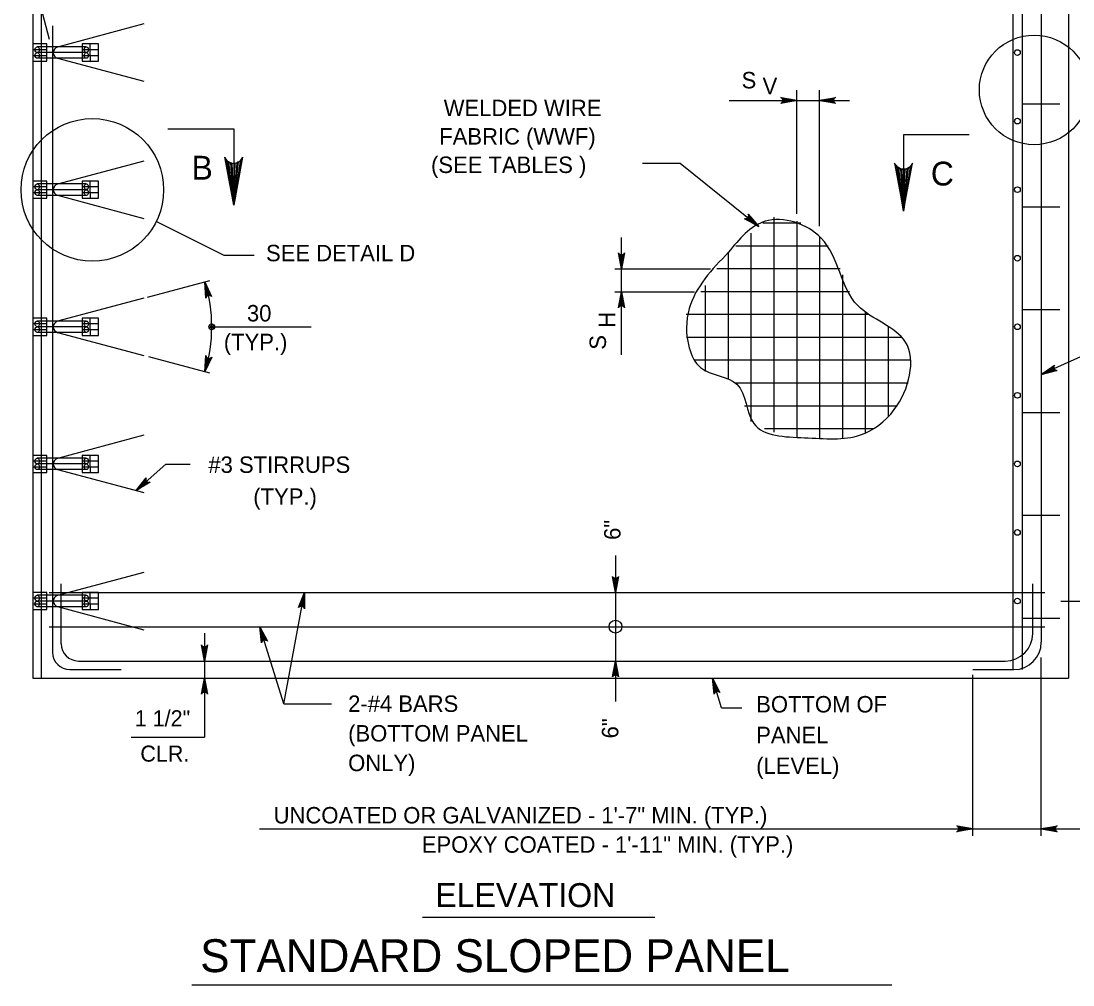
# Model space of a CAD drawing. Extents: x 3385 to 6532, y -616 to 1166.
# Drawn here: x 5133.3 to 5329.7, y 272.4 to 452.4 of the extents above; entities that cross this region are included whole.
import ezdxf

# ---------------------------------------------------------------- set-up
doc = ezdxf.new("R2010")
doc.units = 0
doc.layers.add('1', color=7, linetype='Continuous')

msp = doc.modelspace()

# ---------------------------------------------------------------- linework, layer by layer
at = {"layer": '1'}
for p, q in [((5135.5, 484.9), (5135.5, 329.7)), ((5137.06, 484.9), (5137.06, 329.7)), ((5318.4, 472.1), (5318.4, 331.3)), ((5320.15, 472.1), (5320.15, 331.3)), ((5328.8, 472.1), (5328.8, 329.7)), ((5323.74, 465.38), (5323.74, 336.42)), ((5138.61, 448.92), (5137.35, 453.64)), ((5156.21, 451.84), (5140.09, 447.52)), ((5139.2, 451.51), (5139.2, 334.5)), ((5146.23, 445.97), (5146.23, 448.1)), ((5145.48, 447.57), (5136.32, 447.57)), ((5145.48, 446.5), (5136.32, 446.5)), ((5146.23, 445.97), (5146.23, 444.9)), ((5145.48, 445.44), (5136.32, 445.44)), ((5140.09, 445.46), (5156.21, 441.14)), ((5278.08, 416.38), (5278.08, 439.45)), ((5282.35, 414.07), (5282.35, 439.45)), ((5265.47, 437.57), (5287.91, 437.57)), ((5320.29, 436.9), (5327.2, 436.9)), ((5160.72, 432.26), (5172.99, 432.26)), ((5172.99, 432.26), (5172.99, 417.99)), ((5310.3, 431.16), (5298.04, 431.16)), ((5298.04, 431.16), (5298.04, 416.9)), ((5156.21, 426.24), (5140.09, 421.92)), ((5249.28, 425.88), (5256.32, 425.88)), ((5256.32, 425.88), (5271.01, 414.01)), ((5146.23, 420.37), (5146.23, 422.5)), ((5145.48, 421.97), (5136.32, 421.97)), ((5145.48, 420.9), (5136.32, 420.9)), ((5146.23, 420.37), (5146.23, 419.3)), ((5145.48, 419.84), (5136.32, 419.84)), ((5140.09, 419.86), (5156.21, 415.54)), ((5320.29, 417.7), (5327.2, 417.7)), ((5171.24, 408.59), (5158.53, 414.93)), ((5278.87, 414.65), (5271.76, 414.65)), ((5273.82, 415.79), (5273.82, 375.64)), ((5278.08, 415.04), (5278.08, 374.75)), ((5269.55, 412.77), (5269.55, 377.6)), ((5245.37, 390.05), (5245.37, 411.96)), ((5283.94, 410.38), (5266.72, 410.38)), ((5282.35, 412.14), (5282.35, 374.37)), ((5176.84, 408.59), (5171.24, 408.59)), ((5265.28, 409.12), (5265.28, 385.48)), ((5244.14, 406.11), (5262.01, 406.11)), ((5286.17, 406.11), (5263.18, 406.11)), ((5286.62, 404.98), (5286.62, 374.45)), ((5156.91, 400.83), (5168.52, 403.94)), ((5261.02, 403.02), (5261.02, 386.97)), ((5156.21, 400.64), (5140.09, 396.32)), ((5244.14, 401.85), (5259.02, 401.85)), ((5287.91, 401.85), (5260.2, 401.85)), ((5146.23, 394.77), (5146.23, 396.9)), ((5291.37, 397.58), (5257.46, 397.58)), ((5290.88, 397.94), (5290.88, 375.43)), ((5320.29, 398.5), (5327.2, 398.5)), ((5145.48, 396.37), (5136.32, 396.37)), ((5145.48, 395.3), (5136.32, 395.3)), ((5146.23, 394.77), (5146.23, 393.7)), ((5168.9, 395.29), (5187.48, 395.29)), ((5295.15, 395.28), (5295.15, 378.54)), ((5145.48, 394.24), (5136.32, 394.24)), ((5140.09, 394.26), (5156.21, 389.94)), ((5297.71, 393.31), (5257.51, 393.31)), ((5335.79, 391.81), (5323.74, 386.42)), ((5168.52, 386.64), (5157.13, 389.7)), ((5299.38, 389.05), (5259.09, 389.05)), ((5298.86, 384.78), (5266.66, 384.78)), ((5296.82, 380.51), (5268.32, 380.51)), ((5320.29, 379.3), (5327.2, 379.3)), ((5156.21, 375.04), (5140.09, 370.72)), ((5292.45, 376.25), (5272.09, 376.25)), ((5146.23, 369.17), (5146.23, 371.3)), ((5145.48, 370.77), (5136.32, 370.77)), ((5145.48, 369.7), (5136.32, 369.7)), ((5146.23, 369.17), (5146.23, 368.1)), ((5160.32, 369.64), (5154.78, 364.73)), ((5160.32, 369.64), (5164.86, 369.64)), ((5145.48, 368.64), (5136.32, 368.64)), ((5140.09, 368.66), (5156.21, 364.34)), ((5320.29, 360.1), (5327.2, 360.1)), ((5244.27, 352.58), (5244.27, 325.36)), ((5156.21, 349.44), (5140.09, 345.12)), ((5138.56, 345.7), (5324.39, 345.7)), ((5140.8, 336.1), (5140.8, 347.3)), ((5146.23, 343.57), (5146.23, 345.7)), ((5182.33, 324.9), (5186.19, 345.7)), ((5322.14, 338.02), (5322.14, 347.3)), ((5145.48, 345.17), (5136.32, 345.17)), ((5145.48, 344.1), (5136.32, 344.1)), ((5327.41, 344.1), (5385.83, 344.1)), ((5145.48, 343.04), (5136.32, 343.04)), ((5140.09, 343.06), (5156.21, 338.75)), ((5146.23, 343.57), (5146.23, 342.5)), ((5320.29, 340.9), (5327.2, 340.9)), ((5138.56, 339.3), (5324.39, 339.3)), ((5167.54, 338.1), (5167.54, 318.71)), ((5182.33, 324.9), (5177.86, 339.3)), ((5144, 332.9), (5317.02, 332.9)), ((5323.74, 300.25), (5323.74, 333.55)), ((5142.4, 331.3), (5152, 331.3)), ((5310.94, 331.3), (5318.62, 331.3)), ((5310.94, 300.25), (5310.94, 330.3)), ((5135.5, 329.7), (5328.8, 329.7)), ((5264.06, 324.18), (5262.34, 329.7)), ((5182.33, 324.9), (5191.22, 324.9)), ((5264.06, 324.18), (5267.86, 324.18)), ((5153.88, 318.71), (5167.54, 318.71)), ((5177.83, 301.58), (5332.44, 301.58)), ((5208.26, 285.1), (5251.58, 285.1)), ((5165.17, 272.42), (5295.87, 272.42))]:
    msp.add_line(p, q, dxfattribs=at)
for points in [[(5135.5, 445.97), (5138.13, 445.97), (5138.13, 448.1), (5135.5, 448.1)], [(5144.72, 445.97), (5147.74, 445.97), (5147.74, 448.1), (5144.72, 448.1)], [(5135.5, 444.9), (5138.13, 444.9), (5138.13, 447.03), (5135.5, 447.03)], [(5144.72, 444.9), (5147.74, 444.9), (5147.74, 447.03), (5144.72, 447.03)], [(5135.5, 420.37), (5138.13, 420.37), (5138.13, 422.5), (5135.5, 422.5)], [(5144.72, 420.37), (5147.74, 420.37), (5147.74, 422.5), (5144.72, 422.5)], [(5135.5, 419.3), (5138.13, 419.3), (5138.13, 421.43), (5135.5, 421.43)], [(5144.72, 419.3), (5147.74, 419.3), (5147.74, 421.43), (5144.72, 421.43)], [(5135.5, 394.77), (5138.13, 394.77), (5138.13, 396.9), (5135.5, 396.9)], [(5144.72, 394.77), (5147.74, 394.77), (5147.74, 396.9), (5144.72, 396.9)], [(5135.5, 393.7), (5138.13, 393.7), (5138.13, 395.83), (5135.5, 395.83)], [(5144.72, 393.7), (5147.74, 393.7), (5147.74, 395.83), (5144.72, 395.83)], [(5135.5, 369.17), (5138.13, 369.17), (5138.13, 371.3), (5135.5, 371.3)], [(5144.72, 369.17), (5147.74, 369.17), (5147.74, 371.3), (5144.72, 371.3)], [(5135.5, 368.1), (5138.13, 368.1), (5138.13, 370.24), (5135.5, 370.24)], [(5144.72, 368.1), (5147.74, 368.1), (5147.74, 370.23), (5144.72, 370.23)], [(5135.5, 343.57), (5138.13, 343.57), (5138.13, 345.7), (5135.5, 345.7)], [(5144.72, 343.57), (5147.74, 343.57), (5147.74, 345.7), (5144.72, 345.7)], [(5135.5, 342.5), (5138.13, 342.5), (5138.13, 344.64), (5135.5, 344.64)], [(5144.72, 342.5), (5147.74, 342.5), (5147.74, 344.63), (5144.72, 344.63)]]:
    msp.add_lwpolyline(points, close=True, dxfattribs=at)
for points in [[(5278.08, 437.57), (5275.1, 437.01), (5275.22, 437.09), (5275.33, 437.17), (5275.39, 437.27), (5275.45, 437.37), (5275.47, 437.47), (5275.48, 437.57), (5275.47, 437.67), (5275.45, 437.77), (5275.39, 437.87), (5275.33, 437.97), (5275.22, 438.05), (5275.1, 438.12), (5278.08, 437.57), (5275.22, 438.05), (5275.33, 437.97), (5278.08, 437.57), (5275.39, 437.87), (5275.45, 437.77), (5278.08, 437.57), (5275.47, 437.67), (5275.48, 437.57), (5278.08, 437.57), (5275.47, 437.47), (5275.45, 437.37), (5278.08, 437.57), (5275.39, 437.27), (5275.33, 437.17), (5278.08, 437.57), (5275.22, 437.09)], [(5282.35, 437.57), (5285.33, 438.12), (5285.22, 438.05), (5285.1, 437.97), (5285.04, 437.87), (5284.99, 437.77), (5284.97, 437.67), (5284.95, 437.57), (5284.97, 437.47), (5284.99, 437.37), (5285.04, 437.27), (5285.1, 437.17), (5285.22, 437.09), (5285.33, 437.01), (5282.35, 437.57), (5285.22, 437.09), (5285.1, 437.17), (5282.35, 437.57), (5285.04, 437.27), (5284.99, 437.37), (5282.35, 437.57), (5284.97, 437.47), (5284.95, 437.57), (5282.35, 437.57), (5284.97, 437.67), (5284.99, 437.77), (5282.35, 437.57), (5285.04, 437.87), (5285.1, 437.97), (5282.35, 437.57), (5285.22, 438.05)], [(5172.99, 417.99), (5171.31, 426.94), (5171.55, 426.6), (5171.79, 426.25), (5172.09, 426.08), (5172.39, 425.9), (5172.69, 425.85), (5172.99, 425.79), (5173.29, 425.85), (5173.59, 425.9), (5173.89, 426.08), (5174.19, 426.25), (5174.43, 426.6), (5174.66, 426.94), (5172.99, 417.99), (5174.43, 426.6), (5174.19, 426.25), (5172.99, 417.99), (5173.89, 426.08), (5173.59, 425.9), (5172.99, 417.99), (5173.29, 425.85), (5172.99, 425.79), (5172.99, 417.99), (5172.69, 425.85), (5172.39, 425.9), (5172.99, 417.99), (5172.09, 426.08), (5171.79, 426.25), (5172.99, 417.99), (5171.55, 426.6)], [(5298.04, 416.9), (5299.71, 425.84), (5299.47, 425.5), (5299.24, 425.16), (5298.94, 424.98), (5298.64, 424.8), (5298.34, 424.75), (5298.04, 424.7), (5297.74, 424.75), (5297.44, 424.8), (5297.14, 424.98), (5296.84, 425.16), (5296.6, 425.5), (5296.36, 425.84), (5298.04, 416.9), (5296.6, 425.5), (5296.84, 425.16), (5298.04, 416.9), (5297.14, 424.98), (5297.44, 424.8), (5298.04, 416.9), (5297.74, 424.75), (5298.04, 424.7), (5298.04, 416.9), (5298.34, 424.75), (5298.64, 424.8), (5298.04, 416.9), (5298.94, 424.98), (5299.24, 425.16), (5298.04, 416.9), (5299.47, 425.5)], [(5271.01, 414.01), (5268.34, 415.45), (5268.48, 415.44), (5268.62, 415.43), (5268.73, 415.47), (5268.84, 415.51), (5268.91, 415.58), (5268.99, 415.65), (5269.04, 415.73), (5269.09, 415.82), (5269.1, 415.94), (5269.12, 416.05), (5269.08, 416.19), (5269.04, 416.32), (5271.01, 414.01), (5269.08, 416.19), (5269.12, 416.05), (5271.01, 414.01), (5269.1, 415.94), (5269.09, 415.82), (5271.01, 414.01), (5269.04, 415.73), (5268.99, 415.65), (5271.01, 414.01), (5268.91, 415.58), (5268.84, 415.51), (5271.01, 414.01), (5268.73, 415.47), (5268.62, 415.43), (5271.01, 414.01), (5268.48, 415.44)], [(5245.37, 406.11), (5244.81, 409.1), (5244.89, 408.98), (5244.97, 408.87), (5245.07, 408.81), (5245.17, 408.75), (5245.27, 408.73), (5245.37, 408.71), (5245.47, 408.73), (5245.57, 408.75), (5245.67, 408.81), (5245.77, 408.87), (5245.85, 408.98), (5245.93, 409.1), (5245.37, 406.11), (5245.85, 408.98), (5245.77, 408.87), (5245.37, 406.11), (5245.67, 408.81), (5245.57, 408.75), (5245.37, 406.11), (5245.47, 408.73), (5245.37, 408.71), (5245.37, 406.11), (5245.27, 408.73), (5245.17, 408.75), (5245.37, 406.11), (5245.07, 408.81), (5244.97, 408.87), (5245.37, 406.11), (5244.89, 408.98)], [(5167.63, 403.7), (5168.87, 400.93), (5168.77, 401.03), (5168.66, 401.12), (5168.55, 401.15), (5168.44, 401.19), (5168.34, 401.18), (5168.24, 401.17), (5168.15, 401.13), (5168.05, 401.09), (5167.97, 401.01), (5167.89, 400.93), (5167.84, 400.8), (5167.79, 400.67), (5167.63, 403.7), (5167.84, 400.8), (5167.89, 400.93), (5167.63, 403.7), (5167.97, 401.01), (5168.05, 401.09), (5167.63, 403.7), (5168.15, 401.13), (5168.24, 401.17), (5167.63, 403.7), (5168.34, 401.18), (5168.44, 401.19), (5167.63, 403.7), (5168.55, 401.15), (5168.66, 401.12), (5167.63, 403.7), (5168.77, 401.03)], [(5245.37, 401.85), (5245.93, 398.87), (5245.85, 398.98), (5245.77, 399.09), (5245.67, 399.15), (5245.57, 399.21), (5245.47, 399.23), (5245.37, 399.25), (5245.27, 399.23), (5245.17, 399.21), (5245.07, 399.15), (5244.97, 399.09), (5244.89, 398.98), (5244.81, 398.87), (5245.37, 401.85), (5244.89, 398.98), (5244.97, 399.09), (5245.37, 401.85), (5245.07, 399.15), (5245.17, 399.21), (5245.37, 401.85), (5245.27, 399.23), (5245.37, 399.25), (5245.37, 401.85), (5245.47, 399.23), (5245.57, 399.21), (5245.37, 401.85), (5245.67, 399.15), (5245.77, 399.09), (5245.37, 401.85), (5245.85, 398.98)], [(5167.63, 386.88), (5167.81, 389.91), (5167.86, 389.78), (5167.91, 389.65), (5167.99, 389.57), (5168.08, 389.49), (5168.17, 389.45), (5168.26, 389.41), (5168.36, 389.4), (5168.46, 389.39), (5168.57, 389.42), (5168.69, 389.46), (5168.79, 389.55), (5168.9, 389.64), (5167.63, 386.88), (5168.79, 389.55), (5168.69, 389.46), (5167.63, 386.88), (5168.57, 389.42), (5168.46, 389.39), (5167.63, 386.88), (5168.36, 389.4), (5168.26, 389.41), (5167.63, 386.88), (5168.17, 389.45), (5168.08, 389.49), (5167.63, 386.88), (5167.99, 389.57), (5167.91, 389.65), (5167.63, 386.88), (5167.86, 389.78)], [(5323.74, 386.42), (5326.23, 388.15), (5326.16, 388.03), (5326.09, 387.91), (5326.07, 387.8), (5326.06, 387.68), (5326.09, 387.58), (5326.11, 387.49), (5326.17, 387.4), (5326.22, 387.32), (5326.32, 387.25), (5326.41, 387.18), (5326.55, 387.16), (5326.69, 387.13), (5323.74, 386.42), (5326.55, 387.16), (5326.41, 387.18), (5323.74, 386.42), (5326.32, 387.25), (5326.22, 387.32), (5323.74, 386.42), (5326.17, 387.4), (5326.11, 387.49), (5323.74, 386.42), (5326.09, 387.58), (5326.06, 387.68), (5323.74, 386.42), (5326.07, 387.8), (5326.09, 387.91), (5323.74, 386.42), (5326.16, 388.03)], [(5154.78, 364.73), (5156.64, 367.12), (5156.57, 366.85), (5156.62, 366.62), (5156.72, 366.45), (5156.88, 366.32), (5157.1, 366.25), (5157.38, 366.29), (5154.78, 364.73), (5157.1, 366.25), (5156.88, 366.32), (5154.78, 364.73), (5156.72, 366.45), (5156.62, 366.62), (5154.78, 364.73), (5156.57, 366.85)], [(5244.27, 345.7), (5243.71, 348.69), (5243.79, 348.57), (5243.87, 348.46), (5243.97, 348.4), (5244.07, 348.34), (5244.17, 348.32), (5244.27, 348.3), (5244.37, 348.32), (5244.47, 348.34), (5244.57, 348.4), (5244.67, 348.46), (5244.75, 348.57), (5244.83, 348.69), (5244.27, 345.7), (5244.75, 348.57), (5244.67, 348.46), (5244.27, 345.7), (5244.57, 348.4), (5244.47, 348.34), (5244.27, 345.7), (5244.37, 348.32), (5244.27, 348.3), (5244.27, 345.7), (5244.17, 348.32), (5244.07, 348.34), (5244.27, 345.7), (5243.97, 348.4), (5243.87, 348.46), (5244.27, 345.7), (5243.79, 348.57)], [(5186.19, 345.7), (5186.19, 342.67), (5186.13, 342.8), (5186.08, 342.92), (5185.99, 343), (5185.9, 343.08), (5185.81, 343.11), (5185.71, 343.15), (5185.61, 343.15), (5185.51, 343.15), (5185.4, 343.11), (5185.29, 343.07), (5185.19, 342.97), (5185.09, 342.87), (5186.19, 345.7), (5185.19, 342.97), (5185.29, 343.07), (5186.19, 345.7), (5185.4, 343.11), (5185.51, 343.15), (5186.19, 345.7), (5185.61, 343.15), (5185.71, 343.15), (5186.19, 345.7), (5185.81, 343.11), (5185.9, 343.08), (5186.19, 345.7), (5185.99, 343), (5186.08, 342.92), (5186.19, 345.7), (5186.13, 342.8)], [(5177.86, 339.3), (5179.28, 336.62), (5179.17, 336.71), (5179.06, 336.79), (5178.95, 336.82), (5178.83, 336.85), (5178.73, 336.83), (5178.63, 336.82), (5178.54, 336.77), (5178.45, 336.73), (5178.37, 336.64), (5178.3, 336.56), (5178.25, 336.42), (5178.21, 336.29), (5177.86, 339.3), (5178.25, 336.42), (5178.3, 336.56), (5177.86, 339.3), (5178.37, 336.64), (5178.45, 336.73), (5177.86, 339.3), (5178.54, 336.77), (5178.63, 336.82), (5177.86, 339.3), (5178.73, 336.83), (5178.83, 336.85), (5177.86, 339.3), (5178.95, 336.82), (5179.06, 336.79), (5177.86, 339.3), (5179.17, 336.71)], [(5167.54, 332.9), (5166.98, 335.89), (5167.06, 335.77), (5167.14, 335.66), (5167.24, 335.6), (5167.34, 335.54), (5167.44, 335.52), (5167.54, 335.5), (5167.64, 335.52), (5167.74, 335.54), (5167.84, 335.6), (5167.94, 335.66), (5168.02, 335.77), (5168.1, 335.89), (5167.54, 332.9), (5168.02, 335.77), (5167.94, 335.66), (5167.54, 332.9), (5167.84, 335.6), (5167.74, 335.54), (5167.54, 332.9), (5167.64, 335.52), (5167.54, 335.5), (5167.54, 332.9), (5167.44, 335.52), (5167.34, 335.54), (5167.54, 332.9), (5167.24, 335.6), (5167.14, 335.66), (5167.54, 332.9), (5167.06, 335.77)], [(5244.27, 332.9), (5244.83, 329.92), (5244.75, 330.04), (5244.67, 330.15), (5244.57, 330.21), (5244.47, 330.27), (5244.37, 330.29), (5244.27, 330.3), (5244.17, 330.29), (5244.07, 330.27), (5243.97, 330.21), (5243.87, 330.15), (5243.79, 330.04), (5243.71, 329.92), (5244.27, 332.9), (5243.79, 330.04), (5243.87, 330.15), (5244.27, 332.9), (5243.97, 330.21), (5244.07, 330.27), (5244.27, 332.9), (5244.17, 330.29), (5244.27, 330.3), (5244.27, 332.9), (5244.37, 330.29), (5244.47, 330.27), (5244.27, 332.9), (5244.57, 330.21), (5244.67, 330.15), (5244.27, 332.9), (5244.75, 330.04)], [(5167.54, 329.7), (5168.1, 326.72), (5168.02, 326.84), (5167.94, 326.95), (5167.84, 327.01), (5167.74, 327.07), (5167.64, 327.09), (5167.54, 327.1), (5167.44, 327.09), (5167.34, 327.07), (5167.24, 327.01), (5167.14, 326.95), (5167.06, 326.84), (5166.98, 326.72), (5167.54, 329.7), (5167.06, 326.84), (5167.14, 326.95), (5167.54, 329.7), (5167.24, 327.01), (5167.34, 327.07), (5167.54, 329.7), (5167.44, 327.09), (5167.54, 327.1), (5167.54, 329.7), (5167.64, 327.09), (5167.74, 327.07), (5167.54, 329.7), (5167.84, 327.01), (5167.94, 326.95), (5167.54, 329.7), (5168.02, 326.84)], [(5262.34, 329.7), (5263.76, 327.02), (5263.65, 327.11), (5263.54, 327.19), (5263.43, 327.22), (5263.31, 327.25), (5263.21, 327.23), (5263.11, 327.22), (5263.02, 327.17), (5262.93, 327.13), (5262.85, 327.04), (5262.78, 326.96), (5262.73, 326.82), (5262.69, 326.69), (5262.34, 329.7), (5262.73, 326.82), (5262.78, 326.96), (5262.34, 329.7), (5262.85, 327.04), (5262.93, 327.13), (5262.34, 329.7), (5263.02, 327.17), (5263.11, 327.22), (5262.34, 329.7), (5263.21, 327.23), (5263.31, 327.25), (5262.34, 329.7), (5263.43, 327.22), (5263.54, 327.19), (5262.34, 329.7), (5263.65, 327.11)], [(5310.94, 301.58), (5307.95, 301.02), (5308.07, 301.1), (5308.18, 301.18), (5308.24, 301.28), (5308.3, 301.38), (5308.32, 301.48), (5308.34, 301.58), (5308.32, 301.68), (5308.3, 301.78), (5308.24, 301.88), (5308.18, 301.98), (5308.07, 302.06), (5307.95, 302.14), (5310.94, 301.58), (5308.07, 302.06), (5308.18, 301.98), (5310.94, 301.58), (5308.24, 301.88), (5308.3, 301.78), (5310.94, 301.58), (5308.32, 301.68), (5308.34, 301.58), (5310.94, 301.58), (5308.32, 301.48), (5308.3, 301.38), (5310.94, 301.58), (5308.24, 301.28), (5308.18, 301.18), (5310.94, 301.58), (5308.07, 301.1)], [(5323.74, 301.58), (5326.72, 302.14), (5326.6, 302.06), (5326.49, 301.98), (5326.43, 301.88), (5326.37, 301.78), (5326.35, 301.68), (5326.34, 301.58), (5326.35, 301.48), (5326.37, 301.38), (5326.43, 301.28), (5326.49, 301.18), (5326.6, 301.1), (5326.72, 301.02), (5323.74, 301.58), (5326.6, 301.1), (5326.49, 301.18), (5323.74, 301.58), (5326.43, 301.28), (5326.37, 301.38), (5323.74, 301.58), (5326.35, 301.48), (5326.34, 301.58), (5323.74, 301.58), (5326.35, 301.68), (5326.37, 301.78), (5323.74, 301.58), (5326.43, 301.88), (5326.49, 301.98), (5323.74, 301.58), (5326.6, 302.06)]]:
    msp.add_lwpolyline(points, dxfattribs=at)
for centre, radius in [((5322.42, 439.53), 10.24), ((5319.28, 446.5), 0.534), ((5146.61, 420.86), 13.31), ((5319.28, 433.7), 0.534), ((5319.28, 420.9), 0.534), ((5319.28, 408.1), 0.534), ((5168.9, 395.29), 0.533), ((5168.9, 395.29), 0.267), ((5319.28, 395.3), 0.534), ((5319.28, 382.5), 0.534), ((5319.28, 369.7), 0.534), ((5319.28, 356.9), 0.534), ((5319.28, 344.1), 0.534), ((5244.26, 339.32), 1.2)]:
    msp.add_circle(centre, radius, dxfattribs=at)
for centre, radius, start, end in [((5140.37, 446.49), 1.07, 105, 255), ((5140.37, 420.89), 1.07, 105, 255), ((5140.37, 395.29), 28.53, 342.8582, 17.1418), ((5140.37, 395.29), 1.07, 105, 255), ((5140.37, 369.69), 1.07, 105, 255), ((5140.37, 344.09), 1.07, 105, 255), ((5317.02, 338.02), 5.12, 270, 360), ((5144, 336.1), 3.2, 180, 270), ((5318.62, 336.42), 5.12, 270, 360), ((5142.4, 334.5), 3.2, 180, 270)]:
    msp.add_arc(centre, radius, start, end, dxfattribs=at)
for centre, major_axis, ratio in [((5136.32, 447.03), (0, 0.534), 0.741868), ((5136.32, 445.97), (0, 0.531), 0.745444), ((5145.48, 447.04), (0, 0.534), 0.741868), ((5145.48, 445.96), (0, 0.534), 0.741868), ((5136.32, 421.43), (0, 0.534), 0.741868), ((5136.32, 420.37), (0, 0.531), 0.745444), ((5145.48, 421.44), (0, 0.534), 0.741868), ((5145.48, 420.36), (0, 0.534), 0.741868), ((5136.32, 395.83), (0, 0.534), 0.741868), ((5136.32, 394.77), (0, 0.531), 0.745444), ((5145.48, 395.84), (0, 0.534), 0.741868), ((5145.48, 394.76), (0, 0.534), 0.741868), ((5136.32, 370.23), (0, 0.534), 0.741868), ((5136.32, 369.17), (0, 0.531), 0.745444), ((5145.48, 370.24), (0, 0.534), 0.741868), ((5145.48, 369.16), (0, 0.534), 0.741868), ((5136.32, 344.63), (0, 0.534), 0.741868), ((5136.32, 343.57), (0, 0.531), 0.745444), ((5145.48, 344.64), (0, 0.534), 0.741868), ((5145.48, 343.57), (0, 0.534), 0.741868)]:
    msp.add_ellipse(centre, major_axis=major_axis, ratio=ratio, dxfattribs=at)
msp.add_spline([(5265.36, 409.23), (5258.02, 398.73), (5258.02, 391.38), (5260.12, 387.71), (5266.93, 384.56), (5270.08, 377.22), (5279.52, 374.59), (5290, 375.12), (5296.3, 379.84), (5298.39, 392.43), (5289.48, 399.26), (5282.66, 411.85), (5272.18, 415), (5265.36, 409.22)], degree=3, dxfattribs=at)

# ---------------------------------------------------------------- texts
for s, height, p in [('S', 3.07, (5267.8, 439.81)), ('V', 3.07, (5271.72, 438.72)), ('WELDED WIRE', 3.072, (5212.2, 434.63)), ('FABRIC (WWF)', 3.072, (5211.36, 429.32)), ('B', 4.45, (5165.13, 422.77)), ('(SEE TABLES )', 3.072, (5209.83, 424.01)), ('C', 4.45, (5303.12, 421.68)), ('SEE DETAIL D', 3.072, (5179.03, 407.53)), ('30', 3.072, (5175.47, 396.3)), ('(TYP.)', 3.072, (5171.15, 390.93)), ('#3 STIRRUPS', 3.072, (5168.27, 368.02)), ('(TYP.)', 3.072, (5176.65, 362.06)), ('2-#4 BARS ', 3.072, (5194.36, 323.4)), ('BOTTOM OF', 3.072, (5270.53, 323.29)), ('1 1/2"', 3, (5154.53, 320.71)), ('(BOTTOM PANEL ', 3.0721, (5194.36, 317.87)), ('PANEL', 3.072, (5270.53, 317.55)), ('CLR.', 3, (5155.57, 314.11)), ('ONLY)', 3.072, (5194.36, 312.34)), ('(LEVEL)', 3.072, (5270.53, 311.81)), ('UNCOATED OR GALVANIZED - 1\'-7" MIN. (TYP.)', 3.072, (5180.45, 302.57)), ('EPOXY COATED - 1\'-11" MIN. (TYP.)', 3.072, (5208.1, 297.1)), ('ELEVATION', 4.477, (5210.62, 286.95)), ('STANDARD SLOPED PANEL', 6.144, (5166.74, 274.81))]:
    msp.add_text(s, height=height, dxfattribs=at).set_placement(p)
for s, height, p in [('H', 3.07, (5244.21, 395.1)), ('S', 3.07, (5242.49, 391.02)), ('6"', 3.072, (5245.2, 355.51)), ('6"', 3.072, (5244.79, 318.45))]:
    msp.add_text(s, height=height, rotation=90, dxfattribs=at).set_placement(p)

doc.saveas('drawing.dxf')
